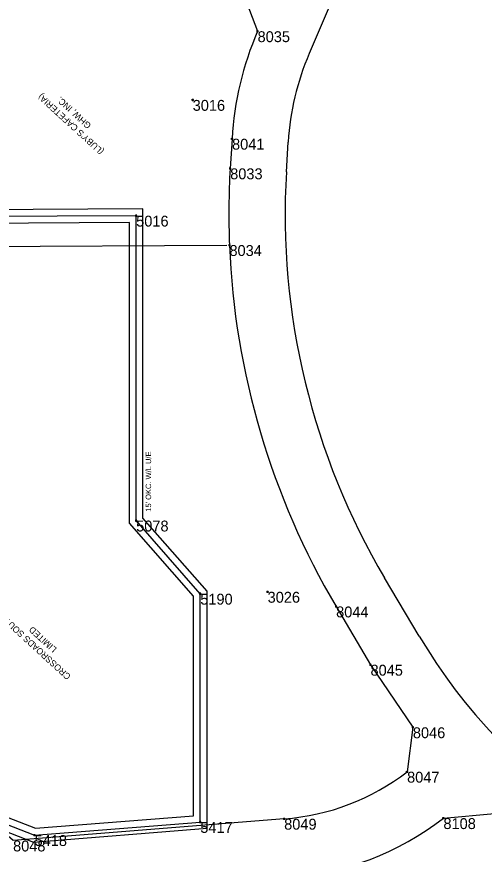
# Model space of a CAD drawing. Extents: x 2145146 to 2158053, y 137507 to 150829.
# Drawn here: x 2151005 to 2151520, y 143925 to 144848 of the extents above; entities that cross this region are included whole.
import ezdxf

# ---------------------------------------------------------------- set-up
doc = ezdxf.new("R2010")
doc.units = 0
for name, color, linetype in [('ALIGN_Cogo Points', 7, 'Continuous'), ('PLSS_Easement', 7, 'Continuous'), ('PLSS_Property Line', 7, 'Continuous'), ('PLSS_Text', 7, 'Continuous'), ('PLSS_Text_TURNED OFF', 7, 'Continuous')]:
    doc.layers.add(name, color=color, linetype=linetype)

msp = doc.modelspace()

# ---------------------------------------------------------------- linework, layer by layer
at = {"layer": 'ALIGN_Cogo Points'}
for points in [[(2151270.67, 144832.3), (2151270.67, 144833.5), (2151270.67, 144832.3), (2151269.47, 144832.3), (2151270.67, 144832.3), (2151270.67, 144831.1), (2151270.67, 144832.3), (2151271.87, 144832.3)], [(2151199.18, 144756.57), (2151199.18, 144757.77), (2151199.18, 144756.57), (2151197.98, 144756.57), (2151199.18, 144756.57), (2151199.18, 144755.37), (2151199.18, 144756.57), (2151200.38, 144756.57)], [(2151242.55, 144713.73), (2151242.55, 144714.93), (2151242.55, 144713.73), (2151241.35, 144713.73), (2151242.55, 144713.73), (2151242.55, 144712.53), (2151242.55, 144713.73), (2151243.75, 144713.73)], [(2151240.48, 144681.07), (2151240.48, 144682.27), (2151240.48, 144681.07), (2151239.28, 144681.07), (2151240.48, 144681.07), (2151240.48, 144679.87), (2151240.48, 144681.07), (2151241.68, 144681.07)], [(2151136.95, 144628.92), (2151136.95, 144630.12), (2151136.95, 144628.92), (2151135.75, 144628.92), (2151136.95, 144628.92), (2151136.95, 144627.72), (2151136.95, 144628.92), (2151138.15, 144628.92)], [(2151239.69, 144596.5), (2151239.69, 144597.7), (2151239.69, 144596.5), (2151238.49, 144596.5), (2151239.69, 144596.5), (2151239.69, 144595.3), (2151239.69, 144596.5), (2151240.89, 144596.5)], [(2151136.93, 144292.7), (2151136.93, 144293.9), (2151136.93, 144292.7), (2151135.73, 144292.7), (2151136.93, 144292.7), (2151136.93, 144291.5), (2151136.93, 144292.7), (2151138.13, 144292.7)], [(2151281.72, 144214.16), (2151281.72, 144215.36), (2151281.72, 144214.16), (2151280.52, 144214.16), (2151281.72, 144214.16), (2151281.72, 144212.96), (2151281.72, 144214.16), (2151282.92, 144214.16)], [(2151207.53, 144212.04), (2151207.53, 144213.24), (2151207.53, 144212.04), (2151206.33, 144212.04), (2151207.53, 144212.04), (2151207.53, 144210.84), (2151207.53, 144212.04), (2151208.73, 144212.04)], [(2151357.18, 144197.97), (2151357.18, 144199.17), (2151357.18, 144197.97), (2151355.98, 144197.97), (2151357.18, 144197.97), (2151357.18, 144196.77), (2151357.18, 144197.97), (2151358.38, 144197.97)], [(2151395.05, 144133.71), (2151395.05, 144134.91), (2151395.05, 144133.71), (2151393.85, 144133.71), (2151395.05, 144133.71), (2151395.05, 144132.51), (2151395.05, 144133.71), (2151396.25, 144133.71)], [(2151441.71, 144064.76), (2151441.71, 144065.96), (2151441.71, 144064.76), (2151440.51, 144064.76), (2151441.71, 144064.76), (2151441.71, 144063.56), (2151441.71, 144064.76), (2151442.91, 144064.76)], [(2151435.35, 144015.75), (2151435.35, 144016.95), (2151435.35, 144015.75), (2151434.15, 144015.75), (2151435.35, 144015.75), (2151435.35, 144014.55), (2151435.35, 144015.75), (2151436.55, 144015.75)], [(2151299.95, 143963.89), (2151299.95, 143965.09), (2151299.95, 143963.89), (2151298.75, 143963.89), (2151299.95, 143963.89), (2151299.95, 143962.69), (2151299.95, 143963.89), (2151301.15, 143963.89)], [(2151475.36, 143964.57), (2151475.36, 143965.77), (2151475.36, 143964.57), (2151474.16, 143964.57), (2151475.36, 143964.57), (2151475.36, 143963.37), (2151475.36, 143964.57), (2151476.56, 143964.57)], [(2151207.58, 143960.33), (2151207.58, 143961.53), (2151207.58, 143960.33), (2151206.38, 143960.33), (2151207.58, 143960.33), (2151207.58, 143959.13), (2151207.58, 143960.33), (2151208.78, 143960.33)], [(2151025.02, 143945.87), (2151025.02, 143947.07), (2151025.02, 143945.87), (2151023.82, 143945.87), (2151025.02, 143945.87), (2151025.02, 143944.67), (2151025.02, 143945.87), (2151026.22, 143945.87)]]:
    msp.add_lwpolyline(points, dxfattribs=at)
at = {"layer": 'PLSS_Easement'}
for points in [[(2150966.29, 143960.36), (2151023.92, 143938.26), (2151215.08, 143953.41), (2151215.03, 144214.86), (2151144.43, 144295.52), (2151144.45, 144636.46), (2150962.64, 144635.49)], [(2150968.98, 143967.36), (2151025.02, 143945.87), (2151207.58, 143960.33), (2151207.53, 144212.04), (2151136.93, 144292.7), (2151136.95, 144628.92), (2150962.68, 144627.99)], [(2150971.66, 143974.36), (2151026.12, 143953.49), (2151200.08, 143967.26), (2151200.03, 144209.22), (2151129.43, 144289.88), (2151129.45, 144621.38), (2150962.72, 144620.49)]]:
    msp.add_lwpolyline(points, dxfattribs=at)
at = {"layer": 'PLSS_Property Line'}
for p, q in [((2151385.43, 144943.51), (2151327.59, 144807.73)), ((2151302.37, 144677.42), (2151304.45, 144710.13)), ((2151448.69, 144165.33), (2151410.58, 144229.48))]:
    msp.add_line(p, q, dxfattribs=at)
for points in [[(2151255.84, 144871.52), (2151255.84, 144871.52), (2151270.67, 144832.3)], [(2151242.55, 144713.73), (2151240.48, 144681.07)], [(2150962.14, 144594.9), (2151236.67, 144596.48)], [(2151357.18, 144197.97), (2151357.18, 144197.97), (2151395.05, 144133.71), (2151441.71, 144064.76), (2151435.35, 144015.75), (2151435.35, 144015.75)], [(2151299.95, 143963.89), (2151299.95, 143963.89), (2151001.37, 143939.89), (2150968.98, 143967.36)], [(2151475.36, 143964.57), (2151475.36, 143964.57), (2151531.48, 143969.57)]]:
    msp.add_lwpolyline(points, dxfattribs=at)
for centre, radius, start, end in [((2151592.49, 144693.38), 350.53, 156.65256, 176.67184), ((2151592.49, 144693.38), 288.53, 156.65256, 176.67184), ((2152091.04, 144630.89), 852.04, 176.624, 182.31364), ((2152091.04, 144630.89), 790.04, 176.624, 210.53729), ((2152091.04, 144630.89), 852.04, 182.31364, 210.53729), ((2151975.89, 144476.64), 612.26, 210.56227, 263.37366), ((2151281.72, 144214.16), 250.93, 274.1663, 307.7519), ((2151281.72, 144214.16), 315.9, 274.09802, 307.80598)]:
    msp.add_arc(centre, radius, start, end, dxfattribs=at)

# ---------------------------------------------------------------- texts
at = {"layer": 'ALIGN_Cogo Points'}
for s, p in [('8035', (2151270.67, 144820.3)), ('3016', (2151199.18, 144744.57)), ('8041', (2151242.55, 144701.73)), ('8033', (2151240.48, 144669.07)), ('5016', (2151136.95, 144616.92)), ('8034', (2151239.69, 144584.5)), ('5078', (2151136.93, 144280.7)), ('3026', (2151281.72, 144202.16)), ('5190', (2151207.53, 144200.04)), ('8044', (2151357.18, 144185.97)), ('8045', (2151395.05, 144121.71)), ('8046', (2151441.71, 144052.76)), ('8047', (2151435.35, 144003.75)), ('5417', (2151207.58, 143948.33)), ('8049', (2151299.95, 143951.89)), ('8108', (2151475.36, 143952.57)), ('8048', (2151001.37, 143927.89)), ('5418', (2151025.02, 143933.87))]:
    msp.add_text(s, height=12, dxfattribs=at).set_placement(p)
at = {"layer": 'PLSS_Text'}
msp.add_text("15' OKC. W/L U/E", height=6, rotation=90, dxfattribs=at).set_placement((2151153.41, 144302.43))
at = {"layer": 'PLSS_Text_TURNED OFF'}
for s, p in [("(LUBY'S CAFETERIA)", (2151101.83, 144700.68)), ('GHW, INC.', (2151088.02, 144729.19)), ('CROSSROADS SOUTH', (2151065.49, 144121.66)), ('LIMITED ', (2151050.02, 144151.69))]:
    msp.add_text(s, height=7, rotation=137.49751, dxfattribs=at).set_placement(p)

doc.saveas('drawing.dxf')
